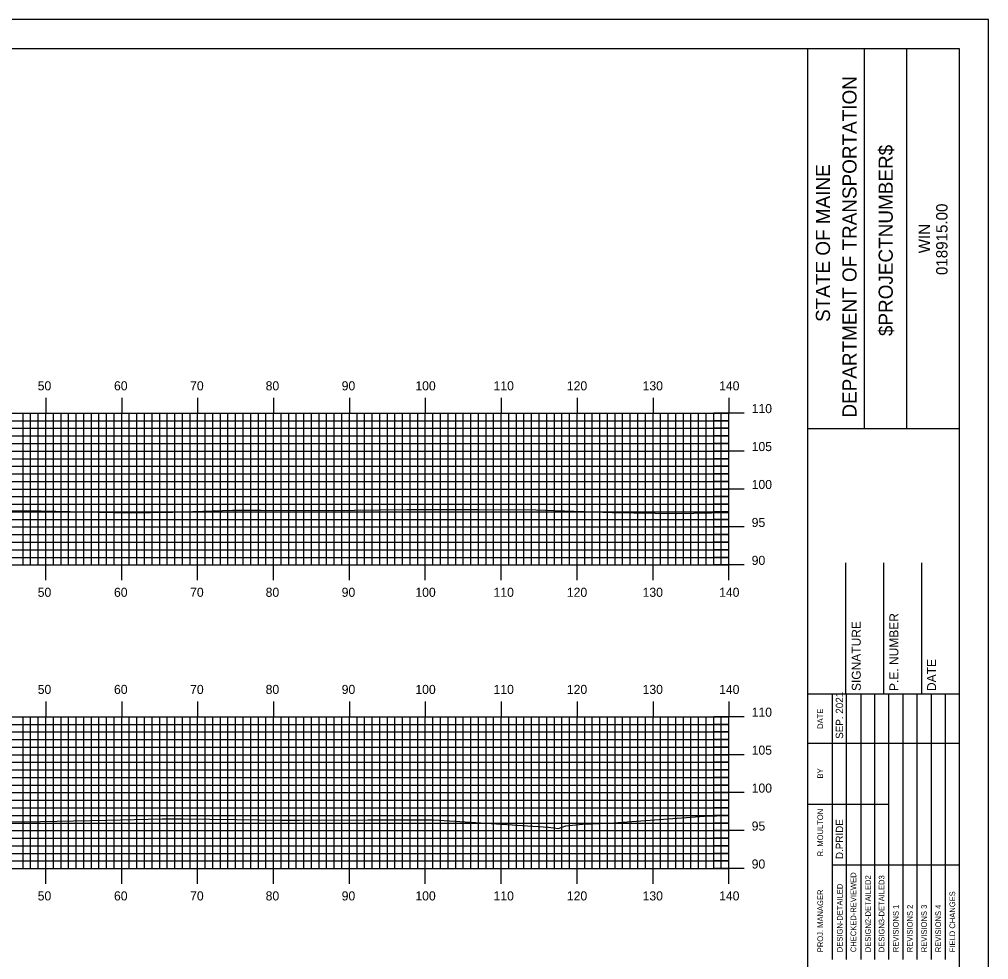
# Model space of a CAD drawing. Extents: x 1764546 to 1764889, y 442591 to 442811.
# Drawn here: x 1764757.9 to 1764885.6, y 442686.7 to 442810.5 of the extents above; entities that cross this region are included whole.
import ezdxf

# ---------------------------------------------------------------- set-up
doc = ezdxf.new("R2010")
doc.units = 0
for name, color, linetype in [('BORDER', 7, 'Continuous'), ('H_V ANNOTATION', 7, 'Continuous'), ('MAJOR', 7, 'Continuous'), ('MINOR', 7, 'Continuous'), ('PLOT BOUNDARY', 7, 'Continuous'), ('S_Roadway_Centerline', 7, 'Continuous')]:
    doc.layers.add(name, color=color, linetype=linetype)

msp = doc.modelspace()

# ---------------------------------------------------------------- linework, layer by layer
at = {"layer": 'BORDER'}
for p, q in [((1764861.74, 442596.67), (1764861.74, 442806.67)), ((1764869.2, 442756.66), (1764869.2, 442806.66)), ((1764874.79, 442756.66), (1764874.79, 442806.66)), ((1764861.75, 442756.65), (1764881.74, 442756.65)), ((1764866.74, 442721.67), (1764866.74, 442738.97)), ((1764871.74, 442721.67), (1764871.74, 442738.97)), ((1764876.74, 442721.67), (1764876.74, 442738.97)), ((1764861.74, 442721.67), (1764881.74, 442721.67))]:
    msp.add_line(p, q, dxfattribs=at)
msp.add_lwpolyline([(1764561.74, 442596.67), (1764881.74, 442596.67), (1764881.74, 442806.67), (1764561.74, 442806.67)], close=True, dxfattribs=at)
for points in [[(1764864.97, 442715.17), (1764864.97, 442721.67)], [(1764866.84, 442686.68), (1764866.84, 442721.67)], [(1764868.7, 442721.67), (1764868.7, 442686.68)], [(1764870.57, 442686.68), (1764870.57, 442721.67)], [(1764872.43, 442686.68), (1764872.43, 442721.67)], [(1764874.29, 442686.68), (1764874.29, 442721.67)], [(1764876.16, 442686.68), (1764876.16, 442721.67)], [(1764878.02, 442686.68), (1764878.02, 442721.67)], [(1764879.88, 442686.68), (1764879.88, 442721.67)], [(1764864.98, 442686.68), (1764864.98, 442720.26)], [(1764861.74, 442715.17), (1764881.74, 442715.17)], [(1764861.74, 442707.17), (1764864.98, 442707.17)], [(1764864.97, 442707.17), (1764872.43, 442707.17)], [(1764864.97, 442699.17), (1764881.74, 442699.17)]]:
    msp.add_lwpolyline(points, dxfattribs=at)
at = {"layer": 'MAJOR'}
for p, q in [((1764761.34, 442760.67), (1764761.34, 442758.67)), ((1764771.34, 442760.67), (1764771.34, 442758.67)), ((1764781.34, 442760.67), (1764781.34, 442758.67)), ((1764791.34, 442760.67), (1764791.34, 442758.67)), ((1764801.34, 442760.67), (1764801.34, 442758.67)), ((1764811.34, 442760.67), (1764811.34, 442758.67)), ((1764821.34, 442760.67), (1764821.34, 442758.67)), ((1764831.34, 442760.67), (1764831.34, 442758.67)), ((1764841.34, 442760.67), (1764841.34, 442758.67)), ((1764851.34, 442760.67), (1764851.34, 442758.67)), ((1764571.34, 442758.67), (1764851.34, 442758.67)), ((1764571.34, 442758.67), (1764851.34, 442758.67)), ((1764761.34, 442738.67), (1764761.34, 442758.67)), ((1764771.34, 442738.67), (1764771.34, 442758.67)), ((1764781.34, 442738.67), (1764781.34, 442758.67)), ((1764791.34, 442738.67), (1764791.34, 442758.67)), ((1764801.34, 442738.67), (1764801.34, 442758.67)), ((1764811.34, 442738.67), (1764811.34, 442758.67)), ((1764821.34, 442738.67), (1764821.34, 442758.67)), ((1764831.34, 442738.67), (1764831.34, 442758.67)), ((1764841.34, 442738.67), (1764841.34, 442758.67)), ((1764853.35, 442758.67), (1764849.34, 442758.67)), ((1764851.34, 442738.67), (1764851.34, 442758.67)), ((1764851.34, 442738.67), (1764851.34, 442758.67)), ((1764571.34, 442753.67), (1764851.34, 442753.67)), ((1764853.35, 442753.67), (1764849.34, 442753.67)), ((1764571.34, 442748.67), (1764851.34, 442748.67)), ((1764853.35, 442748.67), (1764849.34, 442748.67)), ((1764571.34, 442743.67), (1764851.34, 442743.67)), ((1764853.35, 442743.67), (1764849.34, 442743.67)), ((1764571.34, 442738.67), (1764851.34, 442738.67)), ((1764571.34, 442738.67), (1764851.34, 442738.67)), ((1764761.34, 442736.66), (1764761.34, 442738.67)), ((1764771.34, 442736.66), (1764771.34, 442738.67)), ((1764781.34, 442736.66), (1764781.34, 442738.67)), ((1764791.34, 442736.66), (1764791.34, 442738.67)), ((1764801.34, 442736.66), (1764801.34, 442738.67)), ((1764811.34, 442736.66), (1764811.34, 442738.67)), ((1764821.34, 442736.66), (1764821.34, 442738.67)), ((1764831.34, 442736.66), (1764831.34, 442738.67)), ((1764841.34, 442736.66), (1764841.34, 442738.67)), ((1764853.35, 442738.67), (1764849.34, 442738.67)), ((1764851.34, 442736.66), (1764851.34, 442738.67)), ((1764761.34, 442720.67), (1764761.34, 442718.67)), ((1764771.34, 442720.67), (1764771.34, 442718.67)), ((1764781.34, 442720.67), (1764781.34, 442718.67)), ((1764791.34, 442720.67), (1764791.34, 442718.67)), ((1764801.34, 442720.67), (1764801.34, 442718.67)), ((1764811.34, 442720.67), (1764811.34, 442718.67)), ((1764821.34, 442720.67), (1764821.34, 442718.67)), ((1764831.34, 442720.67), (1764831.34, 442718.67)), ((1764841.34, 442720.67), (1764841.34, 442718.67)), ((1764851.34, 442720.67), (1764851.34, 442718.67)), ((1764571.34, 442718.67), (1764851.34, 442718.67)), ((1764571.34, 442718.67), (1764851.34, 442718.67)), ((1764761.34, 442698.67), (1764761.34, 442718.67)), ((1764771.34, 442698.67), (1764771.34, 442718.67)), ((1764781.34, 442698.67), (1764781.34, 442718.67)), ((1764791.34, 442698.67), (1764791.34, 442718.67)), ((1764801.34, 442698.67), (1764801.34, 442718.67)), ((1764811.34, 442698.67), (1764811.34, 442718.67)), ((1764821.34, 442698.67), (1764821.34, 442718.67)), ((1764831.34, 442698.67), (1764831.34, 442718.67)), ((1764841.34, 442698.67), (1764841.34, 442718.67)), ((1764853.35, 442718.67), (1764849.34, 442718.67)), ((1764851.34, 442698.67), (1764851.34, 442718.67)), ((1764851.34, 442698.67), (1764851.34, 442718.67)), ((1764571.34, 442713.67), (1764851.34, 442713.67)), ((1764853.35, 442713.67), (1764849.34, 442713.67)), ((1764571.34, 442708.67), (1764851.34, 442708.67)), ((1764853.35, 442708.67), (1764849.34, 442708.67)), ((1764571.34, 442703.67), (1764851.34, 442703.67)), ((1764853.35, 442703.67), (1764849.34, 442703.67)), ((1764571.34, 442698.67), (1764851.34, 442698.67)), ((1764571.34, 442698.67), (1764851.34, 442698.67)), ((1764761.34, 442696.66), (1764761.34, 442698.67)), ((1764771.34, 442696.66), (1764771.34, 442698.67)), ((1764781.34, 442696.66), (1764781.34, 442698.67)), ((1764791.34, 442696.66), (1764791.34, 442698.67)), ((1764801.34, 442696.66), (1764801.34, 442698.67)), ((1764811.34, 442696.66), (1764811.34, 442698.67)), ((1764821.34, 442696.66), (1764821.34, 442698.67)), ((1764831.34, 442696.66), (1764831.34, 442698.67)), ((1764841.34, 442696.66), (1764841.34, 442698.67)), ((1764853.35, 442698.67), (1764849.34, 442698.67)), ((1764851.34, 442696.66), (1764851.34, 442698.67))]:
    msp.add_line(p, q, dxfattribs=at)
at = {"layer": 'MINOR'}
for p, q in [((1764758.34, 442738.67), (1764758.34, 442758.67)), ((1764759.34, 442738.67), (1764759.34, 442758.67)), ((1764760.34, 442738.67), (1764760.34, 442758.67)), ((1764762.34, 442738.67), (1764762.34, 442758.67)), ((1764763.34, 442738.67), (1764763.34, 442758.67)), ((1764764.34, 442738.67), (1764764.34, 442758.67)), ((1764765.34, 442738.67), (1764765.34, 442758.67)), ((1764766.34, 442738.67), (1764766.34, 442758.67)), ((1764767.34, 442738.67), (1764767.34, 442758.67)), ((1764768.34, 442738.67), (1764768.34, 442758.67)), ((1764769.34, 442738.67), (1764769.34, 442758.67)), ((1764770.34, 442738.67), (1764770.34, 442758.67)), ((1764772.34, 442738.67), (1764772.34, 442758.67)), ((1764773.34, 442738.67), (1764773.34, 442758.67)), ((1764774.34, 442738.67), (1764774.34, 442758.67)), ((1764775.34, 442738.67), (1764775.34, 442758.67)), ((1764776.34, 442738.67), (1764776.34, 442758.67)), ((1764777.34, 442738.67), (1764777.34, 442758.67)), ((1764778.34, 442738.67), (1764778.34, 442758.67)), ((1764779.34, 442738.67), (1764779.34, 442758.67)), ((1764780.34, 442738.67), (1764780.34, 442758.67)), ((1764782.34, 442738.67), (1764782.34, 442758.67)), ((1764783.34, 442738.67), (1764783.34, 442758.67)), ((1764784.34, 442738.67), (1764784.34, 442758.67)), ((1764785.34, 442738.67), (1764785.34, 442758.67)), ((1764786.34, 442738.67), (1764786.34, 442758.67)), ((1764787.34, 442738.67), (1764787.34, 442758.67)), ((1764788.34, 442738.67), (1764788.34, 442758.67)), ((1764789.34, 442738.67), (1764789.34, 442758.67)), ((1764790.34, 442738.67), (1764790.34, 442758.67)), ((1764792.34, 442738.67), (1764792.34, 442758.67)), ((1764793.34, 442738.67), (1764793.34, 442758.67)), ((1764794.34, 442738.67), (1764794.34, 442758.67)), ((1764795.34, 442738.67), (1764795.34, 442758.67)), ((1764796.34, 442738.67), (1764796.34, 442758.67)), ((1764797.34, 442738.67), (1764797.34, 442758.67)), ((1764798.34, 442738.67), (1764798.34, 442758.67)), ((1764799.34, 442738.67), (1764799.34, 442758.67)), ((1764800.34, 442738.67), (1764800.34, 442758.67)), ((1764802.34, 442738.67), (1764802.34, 442758.67)), ((1764803.34, 442738.67), (1764803.34, 442758.67)), ((1764804.34, 442738.67), (1764804.34, 442758.67)), ((1764805.34, 442738.67), (1764805.34, 442758.67)), ((1764806.34, 442738.67), (1764806.34, 442758.67)), ((1764807.34, 442738.67), (1764807.34, 442758.67)), ((1764808.34, 442738.67), (1764808.34, 442758.67)), ((1764809.34, 442738.67), (1764809.34, 442758.67)), ((1764810.34, 442738.67), (1764810.34, 442758.67)), ((1764812.34, 442738.67), (1764812.34, 442758.67)), ((1764813.34, 442738.67), (1764813.34, 442758.67)), ((1764814.34, 442738.67), (1764814.34, 442758.67)), ((1764815.34, 442738.67), (1764815.34, 442758.67)), ((1764816.34, 442738.67), (1764816.34, 442758.67)), ((1764817.34, 442738.67), (1764817.34, 442758.67)), ((1764818.34, 442738.67), (1764818.34, 442758.67)), ((1764819.34, 442738.67), (1764819.34, 442758.67)), ((1764820.34, 442738.67), (1764820.34, 442758.67)), ((1764822.34, 442738.67), (1764822.34, 442758.67)), ((1764823.34, 442738.67), (1764823.34, 442758.67)), ((1764824.34, 442738.67), (1764824.34, 442758.67)), ((1764825.34, 442738.67), (1764825.34, 442758.67)), ((1764826.34, 442738.67), (1764826.34, 442758.67)), ((1764827.34, 442738.67), (1764827.34, 442758.67)), ((1764828.34, 442738.67), (1764828.34, 442758.67)), ((1764829.34, 442738.67), (1764829.34, 442758.67)), ((1764830.34, 442738.67), (1764830.34, 442758.67)), ((1764832.34, 442738.67), (1764832.34, 442758.67)), ((1764833.34, 442738.67), (1764833.34, 442758.67)), ((1764834.34, 442738.67), (1764834.34, 442758.67)), ((1764835.34, 442738.67), (1764835.34, 442758.67)), ((1764836.34, 442738.67), (1764836.34, 442758.67)), ((1764837.34, 442738.67), (1764837.34, 442758.67)), ((1764838.34, 442738.67), (1764838.34, 442758.67)), ((1764839.34, 442738.67), (1764839.34, 442758.67)), ((1764840.34, 442738.67), (1764840.34, 442758.67)), ((1764842.34, 442738.67), (1764842.34, 442758.67)), ((1764843.34, 442738.67), (1764843.34, 442758.67)), ((1764844.34, 442738.67), (1764844.34, 442758.67)), ((1764845.34, 442738.67), (1764845.34, 442758.67)), ((1764846.34, 442738.67), (1764846.34, 442758.67)), ((1764847.34, 442738.67), (1764847.34, 442758.67)), ((1764848.34, 442738.67), (1764848.34, 442758.67)), ((1764849.34, 442738.67), (1764849.34, 442758.67)), ((1764850.34, 442738.67), (1764850.34, 442758.67)), ((1764571.34, 442757.67), (1764851.34, 442757.67)), ((1764851.34, 442757.67), (1764849.34, 442757.67)), ((1764571.34, 442756.67), (1764851.34, 442756.67)), ((1764571.34, 442755.67), (1764851.34, 442755.67)), ((1764851.34, 442756.67), (1764849.34, 442756.67)), ((1764851.34, 442755.67), (1764849.34, 442755.67)), ((1764571.34, 442754.67), (1764851.34, 442754.67)), ((1764851.34, 442754.67), (1764849.34, 442754.67)), ((1764571.34, 442752.67), (1764851.34, 442752.67)), ((1764851.34, 442752.67), (1764849.34, 442752.67)), ((1764571.34, 442751.67), (1764851.34, 442751.67)), ((1764571.34, 442750.67), (1764851.34, 442750.67)), ((1764851.34, 442751.67), (1764849.34, 442751.67)), ((1764851.34, 442750.67), (1764849.34, 442750.67)), ((1764571.34, 442749.67), (1764851.34, 442749.67)), ((1764851.34, 442749.67), (1764849.34, 442749.67)), ((1764571.34, 442747.67), (1764851.34, 442747.67)), ((1764571.34, 442746.67), (1764851.34, 442746.67)), ((1764851.34, 442747.67), (1764849.34, 442747.67)), ((1764851.34, 442746.67), (1764849.34, 442746.67)), ((1764571.34, 442745.67), (1764851.34, 442745.67)), ((1764851.34, 442745.67), (1764849.34, 442745.67)), ((1764571.34, 442744.67), (1764851.34, 442744.67)), ((1764851.34, 442744.67), (1764849.34, 442744.67)), ((1764571.34, 442742.67), (1764851.34, 442742.67)), ((1764571.34, 442741.67), (1764851.34, 442741.67)), ((1764851.34, 442742.67), (1764849.34, 442742.67)), ((1764851.34, 442741.67), (1764849.34, 442741.67)), ((1764571.34, 442740.67), (1764851.34, 442740.67)), ((1764851.34, 442740.67), (1764849.34, 442740.67)), ((1764571.34, 442739.67), (1764851.34, 442739.67)), ((1764851.34, 442739.67), (1764849.34, 442739.67)), ((1764758.34, 442698.67), (1764758.34, 442718.67)), ((1764759.34, 442698.67), (1764759.34, 442718.67)), ((1764760.34, 442698.67), (1764760.34, 442718.67)), ((1764762.34, 442698.67), (1764762.34, 442718.67)), ((1764763.34, 442698.67), (1764763.34, 442718.67)), ((1764764.34, 442698.67), (1764764.34, 442718.67)), ((1764765.34, 442698.67), (1764765.34, 442718.67)), ((1764766.34, 442698.67), (1764766.34, 442718.67)), ((1764767.34, 442698.67), (1764767.34, 442718.67)), ((1764768.34, 442698.67), (1764768.34, 442718.67)), ((1764769.34, 442698.67), (1764769.34, 442718.67)), ((1764770.34, 442698.67), (1764770.34, 442718.67)), ((1764772.34, 442698.67), (1764772.34, 442718.67)), ((1764773.34, 442698.67), (1764773.34, 442718.67)), ((1764774.34, 442698.67), (1764774.34, 442718.67)), ((1764775.34, 442698.67), (1764775.34, 442718.67)), ((1764776.34, 442698.67), (1764776.34, 442718.67)), ((1764777.34, 442698.67), (1764777.34, 442718.67)), ((1764778.34, 442698.67), (1764778.34, 442718.67)), ((1764779.34, 442698.67), (1764779.34, 442718.67)), ((1764780.34, 442698.67), (1764780.34, 442718.67)), ((1764782.34, 442698.67), (1764782.34, 442718.67)), ((1764783.34, 442698.67), (1764783.34, 442718.67)), ((1764784.34, 442698.67), (1764784.34, 442718.67)), ((1764785.34, 442698.67), (1764785.34, 442718.67)), ((1764786.34, 442698.67), (1764786.34, 442718.67)), ((1764787.34, 442698.67), (1764787.34, 442718.67)), ((1764788.34, 442698.67), (1764788.34, 442718.67)), ((1764789.34, 442698.67), (1764789.34, 442718.67)), ((1764790.34, 442698.67), (1764790.34, 442718.67)), ((1764792.34, 442698.67), (1764792.34, 442718.67)), ((1764793.34, 442698.67), (1764793.34, 442718.67)), ((1764794.34, 442698.67), (1764794.34, 442718.67)), ((1764795.34, 442698.67), (1764795.34, 442718.67)), ((1764796.34, 442698.67), (1764796.34, 442718.67)), ((1764797.34, 442698.67), (1764797.34, 442718.67)), ((1764798.34, 442698.67), (1764798.34, 442718.67)), ((1764799.34, 442698.67), (1764799.34, 442718.67)), ((1764800.34, 442698.67), (1764800.34, 442718.67)), ((1764802.34, 442698.67), (1764802.34, 442718.67)), ((1764803.34, 442698.67), (1764803.34, 442718.67)), ((1764804.34, 442698.67), (1764804.34, 442718.67)), ((1764805.34, 442698.67), (1764805.34, 442718.67)), ((1764806.34, 442698.67), (1764806.34, 442718.67)), ((1764807.34, 442698.67), (1764807.34, 442718.67)), ((1764808.34, 442698.67), (1764808.34, 442718.67)), ((1764809.34, 442698.67), (1764809.34, 442718.67)), ((1764810.34, 442698.67), (1764810.34, 442718.67)), ((1764812.34, 442698.67), (1764812.34, 442718.67)), ((1764813.34, 442698.67), (1764813.34, 442718.67)), ((1764814.34, 442698.67), (1764814.34, 442718.67)), ((1764815.34, 442698.67), (1764815.34, 442718.67)), ((1764816.34, 442698.67), (1764816.34, 442718.67)), ((1764817.34, 442698.67), (1764817.34, 442718.67)), ((1764818.34, 442698.67), (1764818.34, 442718.67)), ((1764819.34, 442698.67), (1764819.34, 442718.67)), ((1764820.34, 442698.67), (1764820.34, 442718.67)), ((1764822.34, 442698.67), (1764822.34, 442718.67)), ((1764823.34, 442698.67), (1764823.34, 442718.67)), ((1764824.34, 442698.67), (1764824.34, 442718.67)), ((1764825.34, 442698.67), (1764825.34, 442718.67)), ((1764826.34, 442698.67), (1764826.34, 442718.67)), ((1764827.34, 442698.67), (1764827.34, 442718.67)), ((1764828.34, 442698.67), (1764828.34, 442718.67)), ((1764829.34, 442698.67), (1764829.34, 442718.67)), ((1764830.34, 442698.67), (1764830.34, 442718.67)), ((1764832.34, 442698.67), (1764832.34, 442718.67)), ((1764833.34, 442698.67), (1764833.34, 442718.67)), ((1764834.34, 442698.67), (1764834.34, 442718.67)), ((1764835.34, 442698.67), (1764835.34, 442718.67)), ((1764836.34, 442698.67), (1764836.34, 442718.67)), ((1764837.34, 442698.67), (1764837.34, 442718.67)), ((1764838.34, 442698.67), (1764838.34, 442718.67)), ((1764839.34, 442698.67), (1764839.34, 442718.67)), ((1764840.34, 442698.67), (1764840.34, 442718.67)), ((1764842.34, 442698.67), (1764842.34, 442718.67)), ((1764843.34, 442698.67), (1764843.34, 442718.67)), ((1764844.34, 442698.67), (1764844.34, 442718.67)), ((1764845.34, 442698.67), (1764845.34, 442718.67)), ((1764846.34, 442698.67), (1764846.34, 442718.67)), ((1764847.34, 442698.67), (1764847.34, 442718.67)), ((1764848.34, 442698.67), (1764848.34, 442718.67)), ((1764849.34, 442698.67), (1764849.34, 442718.67)), ((1764850.34, 442698.67), (1764850.34, 442718.67)), ((1764571.34, 442717.67), (1764851.34, 442717.67)), ((1764851.34, 442717.67), (1764849.34, 442717.67)), ((1764571.34, 442716.67), (1764851.34, 442716.67)), ((1764851.34, 442716.67), (1764849.34, 442716.67)), ((1764571.34, 442715.67), (1764851.34, 442715.67)), ((1764571.34, 442714.67), (1764851.34, 442714.67)), ((1764851.34, 442715.67), (1764849.34, 442715.67)), ((1764851.34, 442714.67), (1764849.34, 442714.67)), ((1764571.34, 442712.67), (1764851.34, 442712.67)), ((1764851.34, 442712.67), (1764849.34, 442712.67)), ((1764571.34, 442711.67), (1764851.34, 442711.67)), ((1764851.34, 442711.67), (1764849.34, 442711.67)), ((1764571.34, 442710.67), (1764851.34, 442710.67)), ((1764571.34, 442709.67), (1764851.34, 442709.67)), ((1764851.34, 442710.67), (1764849.34, 442710.67)), ((1764851.34, 442709.67), (1764849.34, 442709.67)), ((1764571.34, 442707.67), (1764851.34, 442707.67)), ((1764851.34, 442707.67), (1764849.34, 442707.67)), ((1764571.34, 442706.67), (1764851.34, 442706.67)), ((1764851.34, 442706.67), (1764849.34, 442706.67)), ((1764571.34, 442705.67), (1764851.34, 442705.67)), ((1764571.34, 442704.67), (1764851.34, 442704.67)), ((1764851.34, 442705.67), (1764849.34, 442705.67)), ((1764851.34, 442704.67), (1764849.34, 442704.67)), ((1764571.34, 442702.67), (1764851.34, 442702.67)), ((1764851.34, 442702.67), (1764849.34, 442702.67)), ((1764571.34, 442701.67), (1764851.34, 442701.67)), ((1764571.34, 442700.67), (1764851.34, 442700.67)), ((1764851.34, 442701.67), (1764849.34, 442701.67)), ((1764851.34, 442700.67), (1764849.34, 442700.67)), ((1764571.34, 442699.67), (1764851.34, 442699.67)), ((1764851.34, 442699.67), (1764849.34, 442699.67))]:
    msp.add_line(p, q, dxfattribs=at)
at = {"layer": 'PLOT BOUNDARY'}
msp.add_lwpolyline([(1764545.56, 442590.55), (1764885.56, 442590.55), (1764885.56, 442810.55), (1764545.56, 442810.55)], close=True, dxfattribs=at)
at = {"layer": 'S_Roadway_Centerline'}
for points in [[(1764754.51, 442745.83), (1764760.71, 442745.78), (1764772.24, 442745.55), (1764778.06, 442745.63), (1764785.92, 442745.89), (1764789.71, 442745.88), (1764798.53, 442745.86), (1764808.9, 442745.98), (1764818.4, 442745.97), (1764825.9, 442745.93), (1764835.99, 442745.6), (1764844.42, 442745.44), (1764851.34, 442745.56)], [(1764755.96, 442704.89), (1764758.48, 442704.83), (1764769.34, 442705.04), (1764776.68, 442705.21), (1764779.45, 442705.22), (1764786.48, 442705.13), (1764792.42, 442705.04), (1764794.78, 442705.05), (1764803.76, 442705.1), (1764812.45, 442705.09), (1764827.57, 442704.14), (1764828.88, 442703.97), (1764829.85, 442704.31), (1764832.04, 442704.54), (1764835.55, 442704.63), (1764848.14, 442705.58), (1764851.34, 442705.68)]]:
    msp.add_lwpolyline(points, dxfattribs=at)

# ---------------------------------------------------------------- texts
at = {"layer": 'BORDER'}
for s, height, p in [('DEPARTMENT OF TRANSPORTATION', 1.8635, (1764868.16, 442758.08)), ('$PROJECTNUMBER$', 1.8635, (1764872.93, 442768.82)), ('STATE OF MAINE', 1.8635, (1764864.66, 442770.69)), ('018915.00', 1.491, (1764880.14, 442776.86)), ('WIN', 1.491, (1764877.82, 442779.73)), ('P.E. NUMBER', 1.1811, (1764873.67, 442722.06)), ('SIGNATURE', 1.181, (1764868.71, 442722.06)), ('DATE', 1.181, (1764878.63, 442722.06)), ('SEP. 2021', 0.969, (1764866.39, 442715.76)), ('DATE', 0.743, (1764863.75, 442717.08)), ('BY', 0.743, (1764863.75, 442710.54)), ('R. MOULTON', 0.745, (1764863.75, 442700.28)), ('D.PRIDE', 0.969, (1764866.39, 442699.92)), ('CHECKED-REVIEWED', 0.7455, (1764868.11, 442687.65)), ('DESIGN2-DETAILED2', 0.7455, (1764870.04, 442687.65)), ('DESIGN3-DETAILED3', 0.7455, (1764871.83, 442687.65)), ('PROJ. MANAGER', 0.7455, (1764863.75, 442687.65)), ('DESIGN-DETAILED', 0.7455, (1764866.32, 442687.65)), ('FIELD CHANGES', 0.7455, (1764881.15, 442687.65)), ('REVISIONS 1', 0.7455, (1764873.7, 442687.65)), ('REVISIONS 2', 0.7455, (1764875.56, 442687.65)), ('REVISIONS 3', 0.7455, (1764877.42, 442687.65)), ('REVISIONS 4', 0.7455, (1764879.29, 442687.65))]:
    msp.add_text(s, height=height, rotation=90, dxfattribs=at).set_placement(p)
at = {"layer": 'H_V ANNOTATION'}
for s, p in [('50', (1764760.27, 442761.67)), ('60', (1764770.32, 442761.67)), ('70', (1764780.35, 442761.67)), ('80', (1764790.3, 442761.67)), ('90', (1764800.32, 442761.67)), ('100', (1764810.03, 442761.67)), ('110', (1764820.33, 442761.67)), ('120', (1764829.99, 442761.67)), ('130', (1764839.97, 442761.67)), ('140', (1764850.05, 442761.67)), ('110', (1764854.34, 442758.67)), ('105', (1764854.34, 442753.67)), ('100', (1764854.34, 442748.67)), ('95', (1764854.34, 442743.67)), ('90', (1764854.34, 442738.67)), ('50', (1764760.27, 442734.47)), ('60', (1764770.32, 442734.47)), ('70', (1764780.35, 442734.47)), ('80', (1764790.3, 442734.47)), ('90', (1764800.32, 442734.47)), ('100', (1764810.03, 442734.47)), ('110', (1764820.33, 442734.47)), ('120', (1764829.99, 442734.47)), ('130', (1764839.97, 442734.47)), ('140', (1764850.05, 442734.47)), ('50', (1764760.27, 442721.67)), ('60', (1764770.32, 442721.67)), ('70', (1764780.35, 442721.67)), ('80', (1764790.3, 442721.67)), ('90', (1764800.32, 442721.67)), ('100', (1764810.03, 442721.67)), ('110', (1764820.33, 442721.67)), ('120', (1764829.99, 442721.67)), ('130', (1764839.97, 442721.67)), ('140', (1764850.05, 442721.67)), ('110', (1764854.34, 442718.67)), ('105', (1764854.34, 442713.67)), ('100', (1764854.34, 442708.67)), ('95', (1764854.34, 442703.67)), ('90', (1764854.34, 442698.67)), ('50', (1764760.27, 442694.47)), ('60', (1764770.32, 442694.47)), ('70', (1764780.35, 442694.47)), ('80', (1764790.3, 442694.47)), ('90', (1764800.32, 442694.47)), ('100', (1764810.03, 442694.47)), ('110', (1764820.33, 442694.47)), ('120', (1764829.99, 442694.47)), ('130', (1764839.97, 442694.47)), ('140', (1764850.05, 442694.47))]:
    msp.add_text(s, height=1.2, dxfattribs=at).set_placement(p)

doc.saveas('drawing.dxf')
